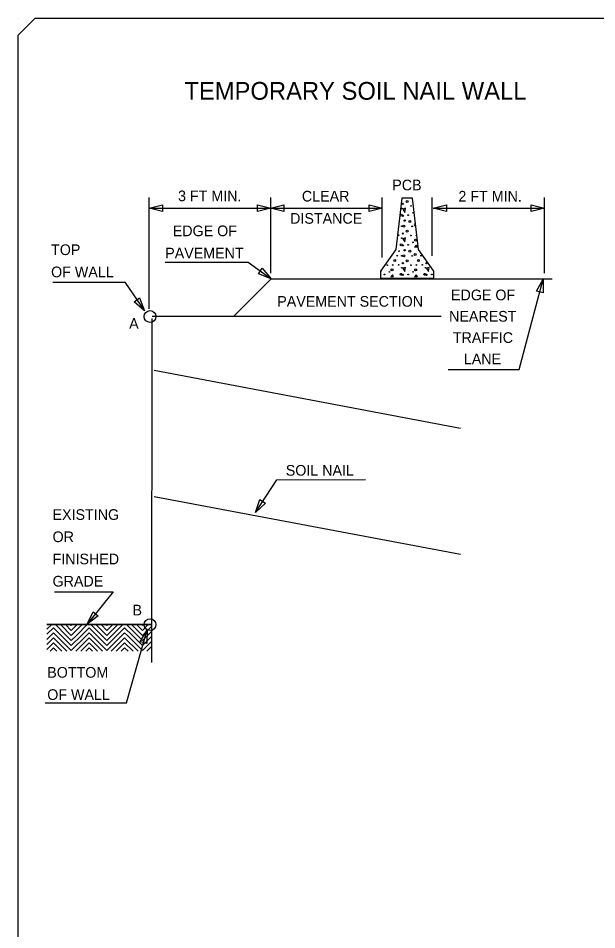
# Model space of a CAD drawing. Extents: x 2487012 to 2497594, y 369516 to 371986.
# Drawn here: x 2487017 to 2487358, y 370720 to 371258 of the extents above; entities that cross this region are included whole.
import ezdxf

# ---------------------------------------------------------------- set-up
doc = ezdxf.new("R2010")
doc.units = 0
for name, color, linetype in [('Scratch_Level_3', 7, 'Continuous'), ('TC LABEL TEMP SHORING', 7, 'Continuous'), ('TC LABEL TEXT', 7, 'Continuous'), ('TC SHEET LAYOUT SHAPE', 7, 'Continuous')]:
    doc.layers.add(name, color=color, linetype=linetype)

msp = doc.modelspace()

# ---------------------------------------------------------------- linework, layer by layer
at = {"layer": 'Scratch_Level_3'}
msp.add_line((2487016.56, 371258.27), (2487016.56, 371258.27), dxfattribs=at)
at = {"layer": 'TC LABEL TEMP SHORING'}
for p, q in [((2487093.87, 371086.68), (2487093.87, 371152.28)), ((2487165.85, 371107.65), (2487165.85, 371152.28)), ((2487231.58, 371117), (2487231.58, 371152.28)), ((2487261, 371117.94), (2487261, 371152.28)), ((2487327.39, 371107.65), (2487327.39, 371152.28)), ((2487095.53, 371080.9), (2487095.23, 370877.67)), ((2487266.45, 371082), (2487095.71, 371082)), ((2487096.89, 371050.32), (2487277.79, 371016.19)), ((2487096.89, 370975.78), (2487277.79, 370941.65)), ((2487033.53, 370897.3), (2487036.34, 370900.1)), ((2487033.53, 370894.33), (2487037.43, 370898.22)), ((2487041.99, 370893.66), (2487037.43, 370898.22)), ((2487044.96, 370893.66), (2487038.53, 370900.1)), ((2487047.93, 370893.66), (2487041.5, 370900.1)), ((2487047.93, 370896.63), (2487044.47, 370900.1)), ((2487047.93, 370899.6), (2487047.44, 370900.1)), ((2487047.93, 370893.66), (2487054.37, 370900.1)), ((2487047.93, 370896.63), (2487051.4, 370900.1)), ((2487047.93, 370899.6), (2487048.43, 370900.1)), ((2487050.9, 370893.66), (2487057.34, 370900.1)), ((2487053.87, 370893.66), (2487058.43, 370898.22)), ((2487062.99, 370893.66), (2487058.43, 370898.22)), ((2487065.96, 370893.66), (2487059.53, 370900.1)), ((2487068.93, 370893.66), (2487062.5, 370900.1)), ((2487068.93, 370896.63), (2487065.47, 370900.1)), ((2487068.93, 370899.6), (2487068.44, 370900.1)), ((2487068.93, 370893.66), (2487075.37, 370900.1)), ((2487068.93, 370896.63), (2487072.4, 370900.1)), ((2487068.93, 370899.6), (2487069.43, 370900.1)), ((2487071.9, 370893.66), (2487078.34, 370900.1)), ((2487074.87, 370893.66), (2487079.43, 370898.22)), ((2487083.99, 370893.66), (2487079.43, 370898.22)), ((2487086.96, 370893.66), (2487080.53, 370900.1)), ((2487089.93, 370893.66), (2487083.5, 370900.1)), ((2487089.93, 370896.63), (2487086.47, 370900.1)), ((2487089.93, 370899.6), (2487089.44, 370900.1)), ((2487089.93, 370896.63), (2487093.4, 370900.1)), ((2487089.93, 370899.6), (2487090.43, 370900.1)), ((2487089.93, 370893.66), (2487095.06, 370898.79)), ((2487033.53, 370891.36), (2487035.84, 370893.66)), ((2487033.53, 370888.39), (2487037.43, 370892.29)), ((2487035.84, 370893.66), (2487037.43, 370895.26)), ((2487039.02, 370893.66), (2487037.43, 370895.26)), ((2487045.37, 370884.35), (2487037.43, 370892.29)), ((2487047.93, 370884.76), (2487039.02, 370893.66)), ((2487047.93, 370887.72), (2487041.99, 370893.66)), ((2487047.93, 370890.69), (2487044.96, 370893.66)), ((2487047.93, 370884.76), (2487056.84, 370893.66)), ((2487047.93, 370887.72), (2487053.87, 370893.66)), ((2487047.93, 370890.69), (2487050.9, 370893.66)), ((2487050.5, 370884.35), (2487058.43, 370892.29)), ((2487056.84, 370893.66), (2487058.43, 370895.26)), ((2487060.02, 370893.66), (2487058.43, 370895.26)), ((2487066.37, 370884.35), (2487058.43, 370892.29)), ((2487068.93, 370884.76), (2487060.02, 370893.66)), ((2487068.93, 370887.72), (2487062.99, 370893.66)), ((2487068.93, 370890.69), (2487065.96, 370893.66)), ((2487068.93, 370884.76), (2487077.84, 370893.66)), ((2487068.93, 370887.72), (2487074.87, 370893.66)), ((2487068.93, 370890.69), (2487071.9, 370893.66)), ((2487071.5, 370884.35), (2487079.43, 370892.29)), ((2487077.84, 370893.66), (2487079.43, 370895.26)), ((2487081.02, 370893.66), (2487079.43, 370895.26)), ((2487087.37, 370884.35), (2487079.43, 370892.29)), ((2487089.93, 370884.76), (2487081.02, 370893.66)), ((2487089.93, 370887.72), (2487083.99, 370893.66)), ((2487089.93, 370890.69), (2487086.96, 370893.66)), ((2487089.93, 370890.69), (2487092.9, 370893.66)), ((2487089.93, 370887.72), (2487095.06, 370892.85)), ((2487092.9, 370893.66), (2487095.06, 370895.82)), ((2487033.53, 370885.42), (2487037.43, 370889.32)), ((2487042.4, 370884.35), (2487037.43, 370889.32)), ((2487053.47, 370884.35), (2487058.43, 370889.32)), ((2487063.4, 370884.35), (2487058.43, 370889.32)), ((2487074.47, 370884.35), (2487079.43, 370889.32)), ((2487084.4, 370884.35), (2487079.43, 370889.32)), ((2487089.93, 370884.76), (2487095.06, 370889.88)), ((2487092.5, 370884.35), (2487095.06, 370886.91)), ((2487035.44, 370884.35), (2487037.43, 370886.35)), ((2487039.43, 370884.35), (2487037.43, 370886.35)), ((2487056.44, 370884.35), (2487058.43, 370886.35)), ((2487060.43, 370884.35), (2487058.43, 370886.35)), ((2487077.44, 370884.35), (2487079.43, 370886.35)), ((2487081.43, 370884.35), (2487079.43, 370886.35))]:
    msp.add_line(p, q, dxfattribs=at)
for points in [[(2487230.58, 371104.8), (2487262.08, 371104.8), (2487262.08, 371108.85), (2487252.98, 371121.69), (2487249.49, 371152.05), (2487243.16, 371152.05), (2487239.68, 371121.69), (2487230.58, 371108.85)], [(2487243.73, 371145.54), (2487244.97, 371143.6), (2487245.36, 371146.08)], [(2487243.73, 371110.54), (2487244.97, 371108.6), (2487245.36, 371111.08)], [(2487257.71, 371110.54), (2487258.95, 371108.6), (2487259.34, 371111.08)], [(2487251.61, 371106.7), (2487250.68, 371105.48), (2487252.33, 371105.8)], [(2487033.53, 370900.1), (2487033.53, 370900.1), (2487095.06, 370900.1), (2487033.53, 370900.1)]]:
    msp.add_lwpolyline(points, close=True, dxfattribs=at)
for points in [[(2487250.8, 371140.63), (2487250.68, 371140.48), (2487250.82, 371140.51)], [(2487243.73, 371128.04), (2487244.97, 371126.1), (2487245.36, 371128.58), (2487243.73, 371128.04)], [(2487251.61, 371124.2), (2487250.68, 371122.98), (2487252.33, 371123.3), (2487251.61, 371124.2)], [(2487230.71, 371109.04), (2487230.99, 371108.6), (2487231.15, 371109.67)], [(2487143.99, 371082.22), (2487165.99, 371104.41), (2487331.97, 371104.31)], [(2487237.63, 371106.7), (2487236.7, 371105.48), (2487238.34, 371105.8), (2487237.63, 371106.7)]]:
    msp.add_lwpolyline(points, dxfattribs=at)
for centre, radius in [((2487246.37, 371150.02), 0.57), ((2487243.12, 371145.9), 0.209), ((2487243.75, 371148.62), 0.386), ((2487248.57, 371147.4), 0.209), ((2487242.79, 371141.98), 0.57), ((2487243.75, 371141.61), 0.386), ((2487246.89, 371141.89), 0.209), ((2487249.79, 371143.39), 0.209), ((2487243.12, 371135.43), 0.209), ((2487244.31, 371135.43), 0.57), ((2487244.87, 371138.71), 0.386), ((2487247.87, 371138.14), 0.57), ((2487249.32, 371135.33), 0.209), ((2487241.25, 371130.09), 0.209), ((2487243.75, 371131.12), 0.386), ((2487246.37, 371132.52), 0.57), ((2487248.57, 371129.9), 0.209), ((2487251.76, 371129.99), 0.209), ((2487242.79, 371124.49), 0.57), ((2487243.12, 371128.4), 0.209), ((2487243.75, 371124.11), 0.386), ((2487246.89, 371124.39), 0.209), ((2487249.79, 371125.89), 0.209), ((2487251.34, 371127.18), 0.57), ((2487240.5, 371118.02), 0.209), ((2487241.53, 371120.64), 0.209), ((2487243.12, 371117.93), 0.209), ((2487244.31, 371117.93), 0.57), ((2487244.87, 371121.21), 0.386), ((2487247.87, 371120.64), 0.57), ((2487249.32, 371117.83), 0.209), ((2487251.06, 371118.77), 0.57), ((2487254.48, 371118.02), 0.209), ((2487234.59, 371112.4), 0.209), ((2487237.78, 371112.49), 0.209), ((2487238.95, 371115.21), 0.57), ((2487241.25, 371112.59), 0.209), ((2487243.75, 371113.62), 0.386), ((2487246.37, 371115.02), 0.57), ((2487248.57, 371112.4), 0.209), ((2487251.76, 371112.49), 0.209), ((2487252.93, 371115.21), 0.57), ((2487255.23, 371112.59), 0.209), ((2487257.73, 371113.62), 0.386), ((2487235.81, 371108.39), 0.209), ((2487237.36, 371109.68), 0.57), ((2487242.79, 371106.99), 0.57), ((2487243.12, 371110.9), 0.209), ((2487249.79, 371108.39), 0.209), ((2487251.34, 371109.68), 0.57), ((2487256.77, 371106.99), 0.57), ((2487257.1, 371110.9), 0.209), ((2487232.91, 371106.89), 0.209), ((2487243.75, 371106.61), 0.386), ((2487246.89, 371106.89), 0.209), ((2487257.73, 371106.61), 0.386), ((2487260.87, 371106.89), 0.209)]:
    msp.add_circle(centre, radius, dxfattribs=at)
for centre, radius, start, end in [((2487241.53, 371138.14), 0.209, 274.5453, 72.3619), ((2487251.06, 371136.27), 0.57, 71.2635, 301.8294), ((2487237.08, 371118.77), 0.57, 284.1214, 5.2003)]:
    msp.add_arc(centre, radius, start, end, dxfattribs=at)
at = {"layer": 'TC LABEL TEXT'}
msp.add_line((2487261.73, 371146.09), (2487327.36, 371146.09), dxfattribs=at)
for points in [[(2487101.8, 371144.03), (2487093.93, 371146), (2487101.8, 371147.97)], [(2487101.8, 371144.03), (2487093.93, 371146), (2487101.8, 371147.97)], [(2487157.89, 371147.97), (2487165.77, 371146), (2487157.89, 371144.03)], [(2487157.89, 371147.97), (2487165.77, 371146), (2487157.89, 371144.03)], [(2487173.37, 371144.03), (2487165.5, 371146), (2487173.37, 371147.97)], [(2487173.37, 371144.03), (2487165.5, 371146), (2487173.37, 371147.97)], [(2487223.79, 371147.97), (2487231.67, 371146), (2487223.79, 371144.03)], [(2487223.79, 371147.97), (2487231.67, 371146), (2487223.79, 371144.03)], [(2487269.6, 371144.12), (2487261.73, 371146.09), (2487269.6, 371148.06)], [(2487269.6, 371144.12), (2487261.73, 371146.09), (2487269.6, 371148.06)], [(2487269.6, 371144.12), (2487261.73, 371146.09), (2487269.6, 371148.06)], [(2487269.6, 371144.12), (2487261.73, 371146.09), (2487269.6, 371148.06)], [(2487319.49, 371148.06), (2487327.36, 371146.09), (2487319.49, 371144.12)], [(2487319.49, 371148.06), (2487327.36, 371146.09), (2487319.49, 371144.12)], [(2487160.7, 371110.56), (2487165.99, 371104.41), (2487158.42, 371107.35)], [(2487160.7, 371110.56), (2487165.99, 371104.41), (2487158.42, 371107.35)], [(2487322.77, 371097.05), (2487326.69, 371104.16), (2487326.57, 371096.04)], [(2487322.77, 371097.05), (2487326.69, 371104.16), (2487326.57, 371096.04)], [(2487322.77, 371097.05), (2487326.69, 371104.16), (2487326.57, 371096.04)], [(2487322.77, 371097.05), (2487326.69, 371104.16), (2487326.57, 371096.04)], [(2487088.27, 371093.04), (2487091.08, 371085.43), (2487085.01, 371090.82)], [(2487088.27, 371093.04), (2487091.08, 371085.43), (2487085.01, 371090.82)], [(2487162.6, 370971.81), (2487156.63, 370966.31), (2487159.31, 370973.97)], [(2487162.6, 370971.81), (2487156.63, 370966.31), (2487159.31, 370973.97)], [(2487063.86, 370905.23), (2487057.38, 370900.33), (2487060.79, 370907.7)], [(2487063.86, 370905.23), (2487057.38, 370900.33), (2487060.79, 370907.7)], [(2487063.86, 370905.23), (2487057.38, 370900.33), (2487060.79, 370907.7)], [(2487063.86, 370905.23), (2487057.38, 370900.33), (2487060.79, 370907.7)], [(2487088.67, 370889.89), (2487092.7, 370896.94), (2487092.46, 370888.82)], [(2487088.67, 370889.89), (2487092.7, 370896.94), (2487092.46, 370888.82)]]:
    msp.add_lwpolyline(points, close=True, dxfattribs=at)
for points in [[(2487093.93, 371146), (2487165.5, 371146), (2487231.67, 371146)], [(2487103.31, 371114.08), (2487152.31, 371114.08), (2487165.99, 371104.41)], [(2487037.07, 371102.43), (2487079.46, 371102.43), (2487091.08, 371085.43)], [(2487270.52, 371050.86), (2487312.55, 371050.86), (2487326.69, 371104.16)], [(2487156.63, 370966.31), (2487169.33, 370985.64), (2487221.73, 370985.86)], [(2487037.97, 370919.35), (2487072.71, 370919.35), (2487057.38, 370900.33)], [(2487032.49, 370853.8), (2487080.54, 370853.8), (2487092.7, 370896.94)]]:
    msp.add_lwpolyline(points, dxfattribs=at)
for centre in [(2487094.43, 371082.06), (2487094.43, 370900.04)]:
    msp.add_circle(centre, 3.48, dxfattribs=at)
at = {"layer": 'TC SHEET LAYOUT SHAPE'}
msp.add_lwpolyline([(2487016.56, 370666.84), (2487016.56, 370976.16), (2487016.56, 371248.27), (2487026.56, 371258.27), (2487469.58, 371258.27), (2487940.56, 371258.27), (2488261.56, 371258.27), (2488261.56, 371178.27), (2488346.56, 371178.27), (2488346.56, 371226.27), (2488506.56, 371226.27), (2488506.56, 370891.3), (2488506.56, 370612.1), (2488506.56, 370360.77), (2488151.56, 370360.77), (2488151.56, 370218.27), (2487778.38, 370218.27), (2487608.92, 370218.27), (2487256.14, 370218.27), (2487016.56, 370218.27)], close=True, dxfattribs=at)

# ---------------------------------------------------------------- texts
at = {"layer": 'TC LABEL TEXT'}
for s, height, p in [('TEMPORARY SOIL NAIL WALL', 10.5, (2487114.72, 371210.12)), ('PCB', 6.3, (2487237.53, 371156.61)), ('3 FT MIN.', 6.3, (2487110.99, 371150.19)), ('CLEAR', 6.3, (2487184.13, 371150.01)), ('2 FT MIN.', 6.3, (2487276.61, 371149.98)), ('DISTANCE', 6.3, (2487177.18, 371136.88)), ('EDGE OF', 6.3, (2487107.85, 371129.52)), ('TOP ', 6.3, (2487035.97, 371118.38)), ('PAVEMENT', 6.3, (2487103.39, 371116.39)), ('OF WALL', 6.3, (2487035.97, 371105.26)), ('EDGE OF', 6.3, (2487272.21, 371091.66)), ('PAVEMENT SECTION', 6.3, (2487169.57, 371087.86)), ('A', 6.3, (2487082.1, 371074.8)), ('NEAREST', 6.3, (2487271.08, 371079.06)), ('TRAFFIC ', 6.3, (2487273.29, 371066.46)), ('LANE', 6.3, (2487279.82, 371053.86)), ('SOIL NAIL', 6.3, (2487174.6, 370988.06)), ('EXISTING', 6.3, (2487036.84, 370961.93)), ('OR', 6.3, (2487036.84, 370948.8)), ('FINISHED', 6.3, (2487036.84, 370935.68)), ('GRADE', 6.3, (2487036.84, 370922.55)), ('B', 6.3, (2487084.06, 370905.5)), ('BOTTOM ', 6.3, (2487033.7, 370868.7)), ('OF WALL', 6.3, (2487033.7, 370855.57))]:
    msp.add_text(s, height=height, dxfattribs=at).set_placement(p)

doc.saveas('drawing.dxf')
